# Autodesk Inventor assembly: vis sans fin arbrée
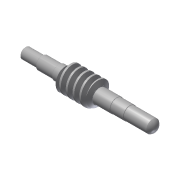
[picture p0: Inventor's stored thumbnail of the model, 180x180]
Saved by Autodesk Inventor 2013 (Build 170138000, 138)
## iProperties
Created: 2011-07
Part Number: vis sans fin arbrée
Document SubType Name: Assembly
Designer: Laur
Author: Laur
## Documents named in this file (3)
- D:\_an13-14\FORMULAIRE_2014\Sujet E4 Poissy-ParisXIXe_janv2012\Modélisation_7970_shimano\pièces mobile vis sans fin\vis sans fin arbrée.iam
- D:\_an13-14\FORMULAIRE_2014\Sujet E4 Poissy-ParisXIXe_janv2012\Modélisation_7970_shimano\pièces mobile vis sans fin\vis sans fin.ipt
- D:\_an13-14\FORMULAIRE_2014\Sujet E4 Poissy-ParisXIXe_janv2012\Modélisation_7970_shimano\vis sans fin arbrée\Design Accelerator\Engrenages à vis sans fin1.iam
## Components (2 placed, 2 different names)
1. vis sans fin:1 — Placage:1, Affleurement:1
2. Engrenages à vis sans fin:1 [sub-assembly] — Placage:1, Affleurement:1
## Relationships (2: Mate 1, Flush 1)
- Placage:1 [Mate]: vis sans fin:1 ↔ Engrenages à vis sans fin:1
- Affleurement:1 [Flush]: vis sans fin:1 ↔ Engrenages à vis sans fin:1
